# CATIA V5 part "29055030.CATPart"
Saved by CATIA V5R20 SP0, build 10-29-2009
Part number: 29055030
Definition: NONE
Nomenclature: 29055030
Source: Unknown
Description: 29055030
Bounding box of the stored display mesh (mm): x -15 to 44.548, y -41.5 to 76.048, z -31.5 to 31.5
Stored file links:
  C:\Users\Utente\Desktop\IO LAVORO\3D X SITO CF\X SITO\PLASTICA\RF1\29055030.CATPart
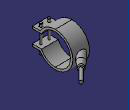
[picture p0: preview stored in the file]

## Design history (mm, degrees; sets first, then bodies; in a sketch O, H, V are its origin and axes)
Body1 "29055030" (main body)
  Solid1: solid without history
